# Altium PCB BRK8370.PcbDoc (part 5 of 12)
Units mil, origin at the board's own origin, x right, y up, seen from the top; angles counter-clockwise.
Board outline 8267.72 x 5708.66 mil, 6 copper layers (L1-TOP, L2-GND, L3-PWR, L4-PWR, L5-GND, L6-BOT), stack 68.606 mil thick; 319 components, 516 nets, 2008 pads, 1743 vias.
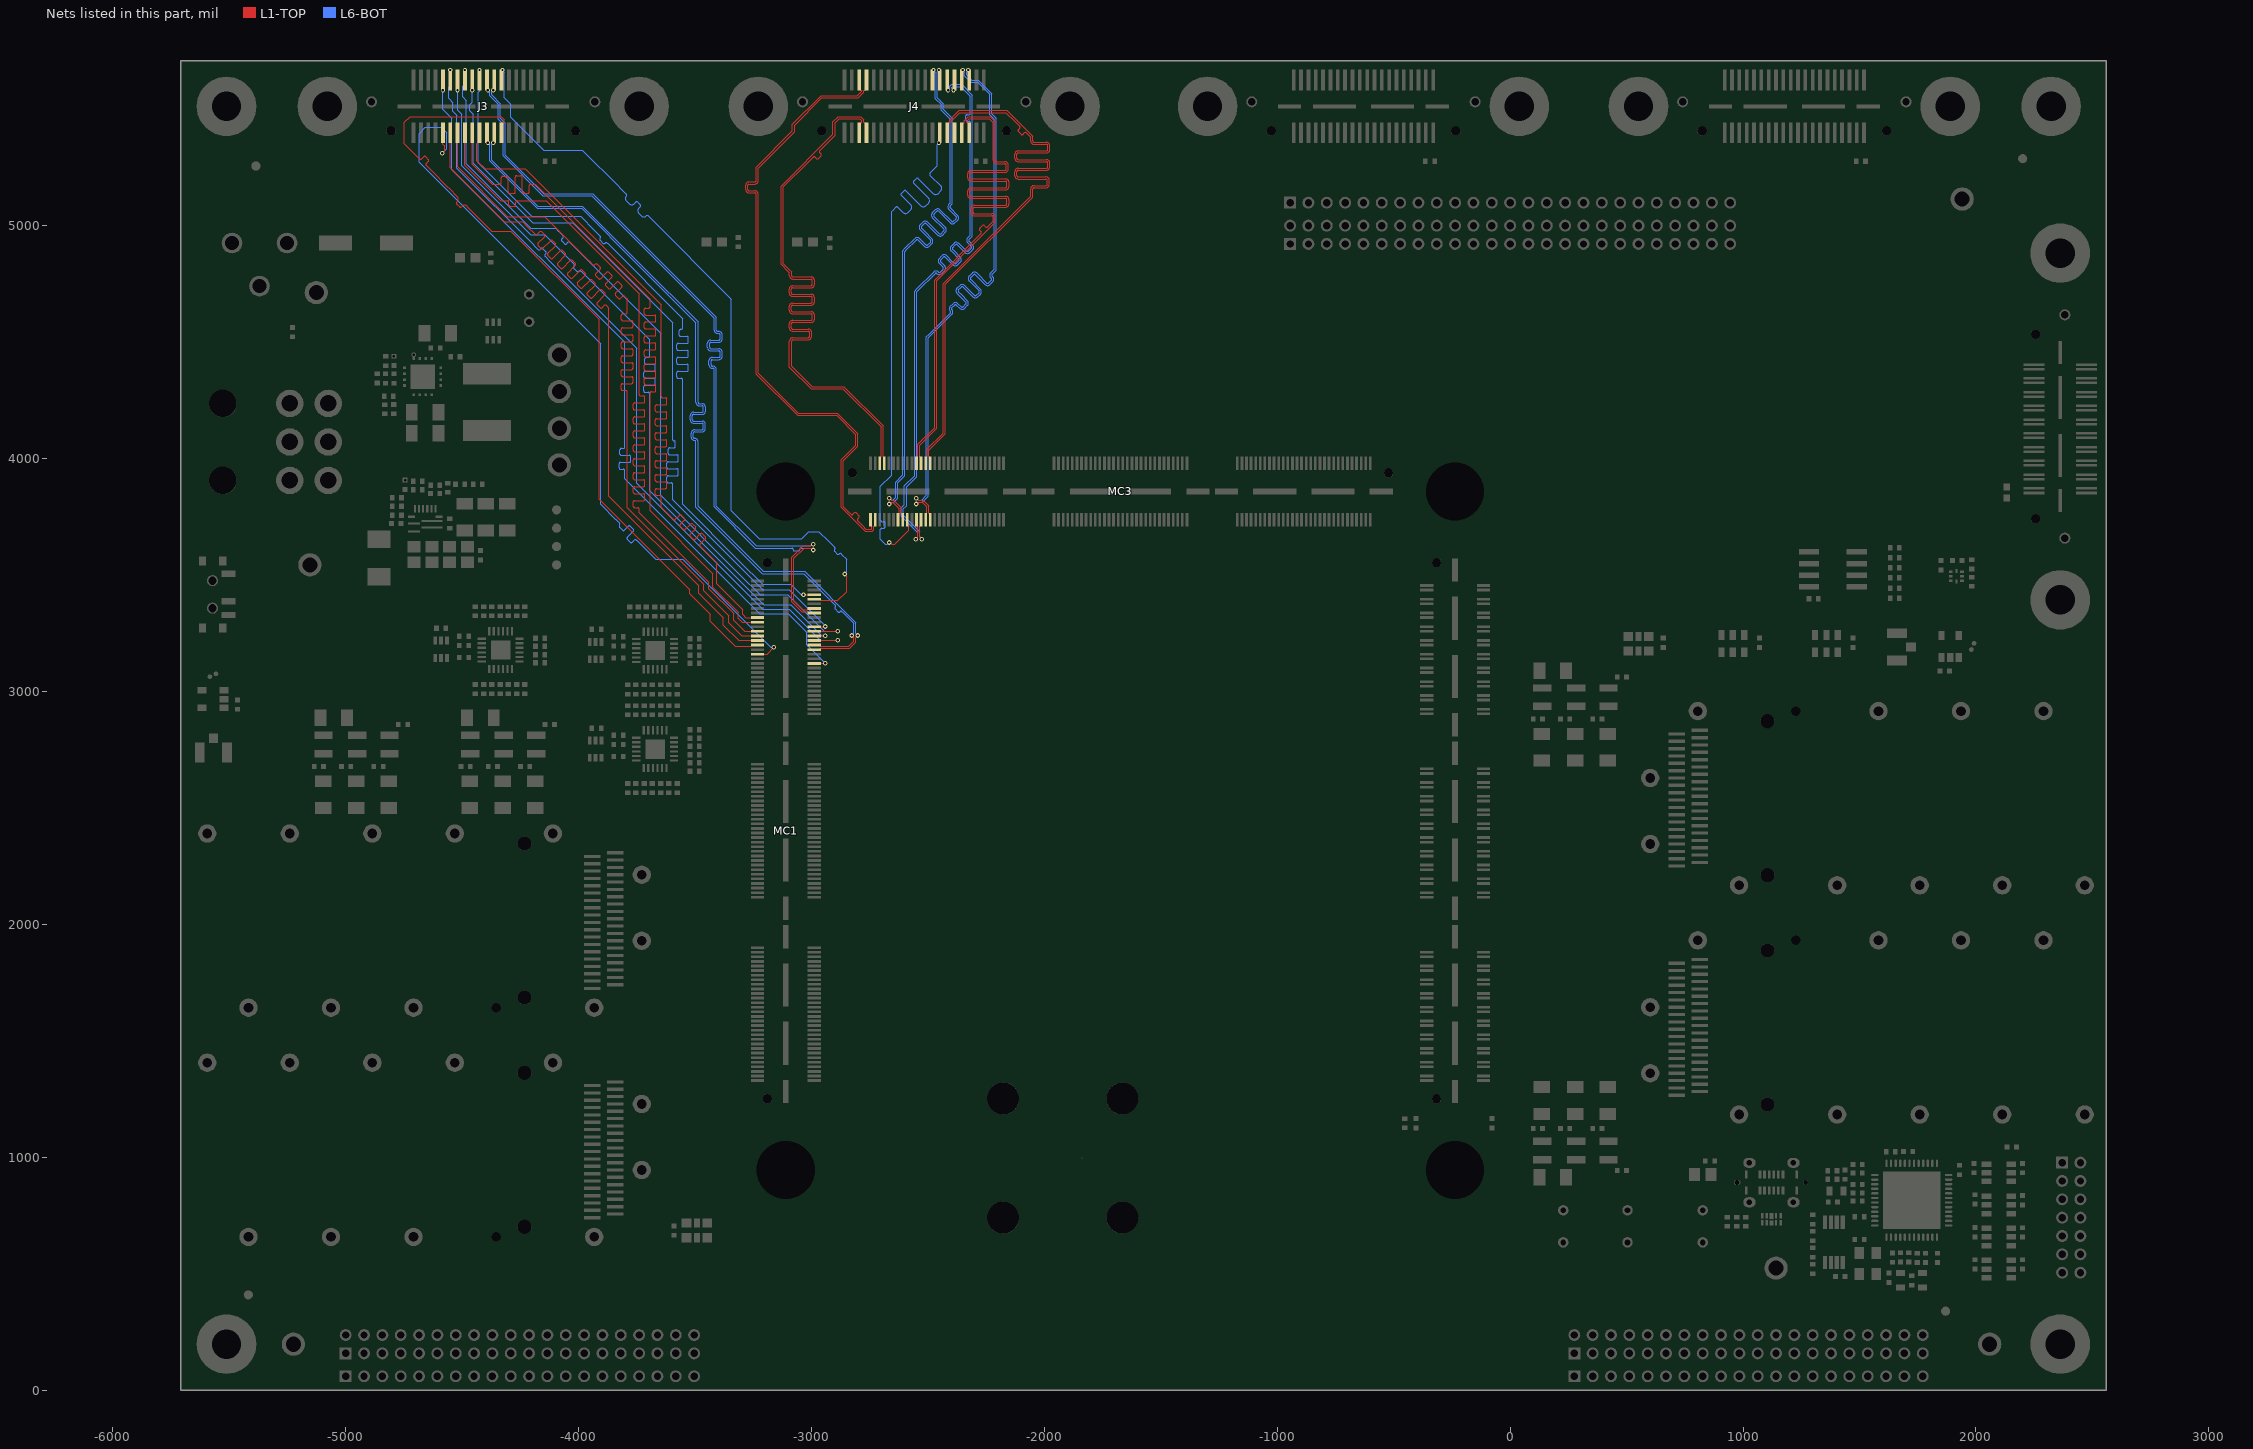
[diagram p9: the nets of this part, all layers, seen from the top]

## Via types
v1: diameter 20, hole 10, L1-TOP to L6-BOT, tented both sides, 957 vias
v2: diameter 18, hole 10, L1-TOP to L6-BOT, tented both sides, 786 vias

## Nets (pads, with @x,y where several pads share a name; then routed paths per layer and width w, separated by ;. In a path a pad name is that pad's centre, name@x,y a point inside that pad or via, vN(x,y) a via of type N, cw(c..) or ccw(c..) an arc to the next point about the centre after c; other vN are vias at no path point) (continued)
PORTA_S10_D4_N: J3.15 MC1.172 | length 3385.4
  L1-TOP w3.3: MC1.172@-2988.58,3395.67 -2965.94,3395.67 -2960.6,3390.33 -2887.61,3390.33 -2849.27,3428.67 -2849.27,3493.65 -2857.27,3501.65 v1(-2857.27,3503.94)
  L6-BOT w3.3: v2(-4326.43,5667.97) -4326.43,5665.72 -4319.4,5658.69 -4319.4,5549.17 -4290.29,5520.07 -4290.29,5464.95 -4149.86,5324.52 -3984.35,5324.52 -3827.76,5167.93 -3824.72,5164.9 -3794.61,5134.78 cw(c-3798.61,5130.78) -3794.61,5126.78 ccw(c-3784.24,5116.41) -3794.59,5106.02 -3782.63,5094.07 ccw(c-3772.24,5104.41) -3761.87,5094.04 -3755.05,5100.87 cw(c-3751.02,5096.89) -3747.02,5100.89 -3735.01,5088.88 cw(c-3739.01,5084.88) -3735.01,5080.88 -3741.86,5074.03 ccw(c-3731.49,5063.66) -3741.84,5053.27 -3729.88,5041.32 ccw(c-3719.49,5051.66) -3709.12,5041.29 cw(c-3705.12,5037.29) -3701.1,5041.27 ; -3701.09,5041.26 -3699.8,5039.97 -3696.77,5036.94 -3343.49,4683.66 -3343.49,3775.64 -3223.79,3655.95 -3042.49,3655.95 -3012.28,3686.16 -2968.04,3686.16 -2928.34,3646.46 -2900.43,3618.56 cw(c-2904.44,3614.56) -2900.43,3610.56 -2901.14,3609.85 ccw(c-2897.14,3605.85) -2901.14,3601.85 -2889.13,3589.84 ccw(c-2885.13,3593.84) -2881.13,3589.84 -2880.42,3590.55 cw(c-2876.42,3586.54) -2872.42,3590.55 -2871.25,3589.38 -2849.27,3567.4 -2849.27,3514.22 -2857.27,3506.22 v1(-2857.27,3503.94)
PORTA_S11_D5_N: J3.16 MC1.151 | length 3562.6
  L1-TOP w3.3: -4520.25,5123.94 -4558.08,5161.77 -4561.11,5164.8 -4633.2,5236.88 -4654.37,5258.06 cw(c-4650.37,5262.06) -4654.37,5266.06 -4644.7,5275.74 ccw(c-4648.7,5279.74) -4644.7,5283.74 -4656.71,5295.75 ccw(c-4660.71,5291.75) -4664.71,5295.75 -4674.39,5286.08 cw(c-4678.39,5290.08) -4682.39,5286.08 -4695.11,5298.79 -4748.03,5351.72 -4748.03,5443.48 -4723.4,5468.11 -4332.66,5468.11 -4319.4,5454.85 -4319.4,5444.04 -4321.33,5442.11 -4324.3,5442.11 -4330.65,5435.76 J3.16@-4330.65,5399.01 ; -4520.24,5123.92 -4518.94,5122.62 -4518.94,5122.43 cw(c-4530.62,5113.57) -4520.25,5103.21 -4523.32,5100.14 ccw(c-4519.32,5096.14) -4523.32,5092.15 -4511.31,5080.13 ccw(c-4507.31,5084.14) -4503.31,5080.13 -4500.24,5083.2 cw(c-4489.88,5072.83) -4481.02,5084.52 -4480.83,5084.52 -4479.53,5083.21 -4478.19,5081.88 -4475.16,5078.85 -4372.69,4976.38 -4291.34,4976.38 -3912.26,4597.3 -3912.26,3825.89 -3522.5,3436.13 -3522.5,3419.24 -3434.2,3330.94 -3434.2,3300.34 -3327.33,3193.48 -3259.87,3193.48 -3254.53,3198.82 MC1.151@-3231.89,3198.82
PORTA_S12_D6_P: J3.17 MC1.166 | length 3385.4
  L1-TOP w3.3: v1(-2992.13,3632.3) -2994.41,3632.3 -3002.41,3624.3 -3035.69,3624.3 -3084.93,3575.06 -3084.93,3385.57 -3041.32,3341.96 -3016.56,3341.96 -3011.22,3336.61 MC1.166@-2988.58,3336.61
  L6-BOT w3.3: v2(-4366.46,5581.25) -4366.46,5579.01 -4373.5,5571.97 -4373.5,5560.88 -4336.41,5523.8 -4336.41,5460.97 -4314.33,5438.88 -4314.33,5302.65 -4149.47,5137.8 -3940.03,5137.8 -3743.18,4940.94 -3408.32,4606.09 -3408.32,4557.53 -3408.32,4551.38 ccw(c-3402.66,4551.38) -3402.66,4545.72 -3397.98,4545.72 cw(c-3397.98,4531.06) -3383.32,4531.06 -3383.32,4514.08 cw(c-3397.98,4514.08) -3397.98,4499.42 -3432.17,4499.42 ccw(c-3432.17,4493.76) -3437.83,4493.76 -3437.83,4476.78 ccw(c-3432.17,4476.78) -3432.17,4471.12 -3397.98,4471.12 cw(c-3397.98,4456.46) -3383.32,4456.46 -3383.32,4439.48 cw(c-3397.98,4439.48) -3397.98,4424.82 -3425.64,4424.82 ccw(c-3425.64,4419.16) -3431.3,4419.16 -3431.3,4402.18 ccw(c-3425.64,4402.18) -3425.64,4396.52 -3422.98,4396.52 cw(c-3422.98,4381.86) -3408.32,4381.86 -3408.32,4305.4 -3408.32,3795.72 -3236.9,3624.3 -3002.41,3624.3 -2994.41,3632.3 v1(-2992.13,3632.3)
PORTA_S13_D7_P: J3.18 MC1.150 | length 3385.4
  L1-TOP w3.3: MC1.150@-2988.58,3179.13 -2965.94,3179.13 -2960.6,3184.48 -2836.64,3184.48 -2809.77,3211.34 -2809.77,3229.87 -2801.77,3237.87 v1(-2801.77,3240.16)
  L6-BOT w3.3: v2(-4366.46,5355.65) -4366.46,5353.41 -4373.5,5346.37 -4373.5,5281.36 -4174.82,5082.68 -3983.34,5082.68 -3735.3,4834.65 -3487.06,4586.41 -3487.06,4247.29 -3487.06,4241.14 ccw(c-3481.4,4241.14) -3481.4,4235.48 -3469.71,4235.48 cw(c-3469.71,4220.82) -3455.05,4220.82 -3455.05,4203.84 cw(c-3469.71,4203.84) -3469.71,4189.18 -3506.4,4189.18 ccw(c-3506.4,4183.52) -3512.06,4183.52 -3512.06,4166.54 ccw(c-3506.4,4166.54) -3506.4,4160.88 -3469.86,4160.88 cw(c-3469.86,4146.22) -3455.2,4146.22 -3455.2,4129.24 cw(c-3469.86,4129.24) -3469.86,4114.58 -3501.72,4114.58 ccw(c-3501.72,4108.92) -3507.38,4108.92 -3507.38,4091.94 ccw(c-3501.72,4091.94) -3501.72,4086.28 cw(c-3501.72,4071.62) -3487.06,4071.62 -3487.06,3997.2 -3487.06,3793.99 -3208.02,3514.95 -3029.19,3514.95 -2809.77,3295.53 -2809.77,3250.44 -2801.77,3242.44 v1(-2801.77,3240.16)
PORTA_S14_D6_N: J3.19 MC1.168 | length 3385.4
  L1-TOP w3.3: v1(-2992.13,3607.3) -2994.41,3607.3 -3002.41,3615.3 -3031.96,3615.3 -3075.93,3571.33 -3075.93,3389.3 -3037.59,3350.96 -3016.56,3350.96 -3011.22,3356.3 MC1.168@-2988.58,3356.3
  L6-BOT w3.3: v2(-4389.53,5581.25) -4389.53,5579.01 -4382.5,5571.97 -4382.5,5557.16 -4345.41,5520.07 -4345.41,5457.24 -4323.33,5435.15 -4323.33,5298.92 -4153.2,5128.8 -3943.76,5128.8 -3755.91,4940.95 -3417.32,4602.36 -3417.32,4557.53 -3417.32,4551.38 ccw(c-3402.66,4551.38) -3402.66,4536.72 -3397.98,4536.72 cw(c-3397.98,4531.06) -3392.32,4531.06 -3392.32,4514.08 cw(c-3397.98,4514.08) -3397.98,4508.42 -3432.17,4508.42 ccw(c-3432.17,4493.76) -3446.83,4493.76 -3446.83,4476.78 ccw(c-3432.17,4476.78) -3432.17,4462.12 -3397.98,4462.12 cw(c-3397.98,4456.46) -3392.32,4456.46 -3392.32,4439.48 cw(c-3397.98,4439.48) -3397.98,4433.82 -3425.64,4433.82 ccw(c-3425.64,4419.16) -3440.3,4419.16 -3440.3,4402.18 ccw(c-3425.64,4402.18) -3425.64,4387.52 -3422.98,4387.52 cw(c-3422.98,4381.86) -3417.32,4381.86 -3417.32,4305.4 -3417.32,3791.99 -3240.63,3615.3 -3102.36,3615.3 -3084.58,3615.3 cw(c-3084.58,3609.64) -3078.92,3609.64 -3078.92,3608.63 ccw(c-3073.26,3608.63) -3073.26,3602.97 -3056.28,3602.97 ccw(c-3056.28,3608.63) -3050.62,3608.63 -3050.62,3609.64 cw(c-3044.96,3609.64) -3044.96,3615.3 -3043.31,3615.3 -3002.41,3615.3 -2994.41,3607.3 v1(-2992.13,3607.3)
PORTA_S15_D7_N: J3.20 MC1.152 | length 3385.4
  L1-TOP w3.3: MC1.152@-2988.58,3198.82 -2965.94,3198.82 -2960.6,3193.48 -2840.37,3193.48 -2818.77,3215.07 -2818.77,3229.87 -2826.77,3237.87 v1(-2826.77,3240.16)
  L6-BOT w3.3: v2(-4389.53,5355.65) -4389.53,5353.41 -4382.5,5346.37 -4382.5,5277.63 -4178.55,5073.68 -3987.06,5073.68 -3748.03,4834.65 -3496.06,4582.68 -3496.06,4247.29 -3496.06,4241.14 ccw(c-3481.4,4241.14) -3481.4,4226.48 -3469.71,4226.48 cw(c-3469.71,4220.82) -3464.05,4220.82 -3464.05,4203.84 cw(c-3469.71,4203.84) -3469.71,4198.18 -3506.4,4198.18 ccw(c-3506.4,4183.52) -3521.06,4183.52 -3521.06,4166.54 ccw(c-3506.4,4166.54) -3506.4,4151.88 -3469.86,4151.88 cw(c-3469.86,4146.22) -3464.2,4146.22 -3464.2,4129.24 cw(c-3469.86,4129.24) -3469.86,4123.58 -3501.72,4123.58 ccw(c-3501.72,4108.92) -3516.38,4108.92 -3516.38,4091.94 ccw(c-3501.72,4091.94) -3501.72,4077.28 cw(c-3501.72,4071.62) -3496.06,4071.62 -3496.06,3997.2 -3496.06,3790.26 -3211.75,3505.95 -3032.92,3505.95 -2921.39,3394.42 -2897.51,3370.54 cw(c-2901.51,3366.54) -2897.51,3362.54 -2898.22,3361.83 ccw(c-2894.22,3357.83) -2898.22,3353.82 -2886.21,3341.82 ccw(c-2882.21,3345.82) -2878.21,3341.82 -2877.5,3342.53 cw(c-2873.5,3338.52) -2869.49,3342.53 -2868.33,3341.36 -2818.77,3291.8 -2818.77,3250.44 -2826.77,3242.44 v1(-2826.77,3240.16)
PORTA_S16: J3.21 MC1.174 | length 3379
  L1-TOP w4.96: v1(-3033.97,3414.88) -3033.74,3415.12 -2988.82,3415.12 MC1.174@-2988.58,3415.35
  L6-BOT w4.96: v2(-4425.25,5667.97) -4425.25,5578.79 -4431.15,5572.88 -4431.15,5270.32 -4200.2,5039.37 -3991.75,5039.37 -3932.88,4980.5 -3931.13,4978.75 -3907.21,4954.83 cw(c-3911.45,4950.6) -3907.21,4946.36 -3908.02,4945.55 ccw(c-3903.78,4941.31) -3908.02,4937.08 -3895.31,4924.36 ccw(c-3891.07,4928.6) -3886.83,4924.36 -3886.03,4925.17 cw(c-3881.79,4920.93) -3877.55,4925.17 -3875.8,4923.42 -3553.33,4600.95 -3553.33,4586.61 -3553.33,4560.09 cw(c-3559.32,4560.09) -3559.32,4554.1 -3561.79,4554.1 ccw(c-3561.79,4548.11) -3567.78,4548.11 -3567.78,4530.13 ccw(c-3561.79,4530.13) -3561.79,4524.14 -3534.32,4524.14 cw(c-3534.32,4518.15) -3528.33,4518.15 -3528.33,4500.17 cw(c-3534.32,4500.17) -3534.32,4494.18 -3572.33,4494.18 ccw(c-3572.33,4488.18) -3578.33,4488.18 -3578.33,4470.21 ccw(c-3572.33,4470.21) -3572.33,4464.21 -3534.32,4464.21 cw(c-3534.32,4458.22) -3528.33,4458.22 -3528.33,4440.24 cw(c-3534.32,4440.24) -3534.32,4434.25 -3572.33,4434.25 ccw(c-3572.33,4428.26) -3578.33,4428.26 -3578.33,4410.28 ccw(c-3572.33,4410.28) -3572.33,4404.29 -3534.32,4404.29 cw(c-3534.32,4398.29) -3528.33,4398.29 -3528.33,4380.32 cw(c-3534.32,4380.32) -3534.32,4374.32 -3572.33,4374.32 ccw(c-3572.33,4368.33) -3578.33,4368.33 -3578.33,4350.35 ccw(c-3572.33,4350.35) -3572.33,4344.36 -3559.32,4344.36 cw(c-3559.32,4338.37) -3553.33,4338.37 -3553.33,4335.89 -3553.33,3803.61 -3307.09,3557.37 -3209.95,3460.23 -3088,3460.23 -3045.53,3417.76 -3040,3417.76 v1@-3037.13,3414.88
PORTA_S17: J3.22 MC1.163 | length 3560.8
  L1-TOP w4.96: J3.22@-4425.15,5399.01 -4425.15,5362.26 -4437.01,5350.4 -4437.01,5279.53 -4401.57,5244.09 -4228.88,5244.09 -3645.67,4660.88 -3645.67,4279.53 -3645.67,4266.59 ccw(c-3639.68,4266.59) -3639.68,4260.6 -3626.66,4260.6 cw(c-3626.66,4254.61) -3620.67,4254.61 -3620.67,4236.63 cw(c-3626.66,4236.63) -3626.66,4230.64 -3664.68,4230.64 ccw(c-3664.68,4224.64) -3670.67,4224.64 -3670.67,4206.67 ccw(c-3664.68,4206.67) -3664.68,4200.67 -3626.66,4200.67 cw(c-3626.66,4194.68) -3620.67,4194.68 -3620.67,4176.7 cw(c-3626.66,4176.7) -3626.66,4170.71 -3664.68,4170.71 ccw(c-3664.68,4164.72) -3670.67,4164.72 -3670.67,4146.74 ccw(c-3664.68,4146.74) -3664.68,4140.75 -3626.66,4140.75 cw(c-3626.66,4134.76) -3620.67,4134.76 -3620.67,4116.78 cw(c-3626.66,4116.78) -3626.66,4110.78 -3664.68,4110.78 ccw(c-3664.68,4104.79) -3670.67,4104.79 -3670.67,4086.81 ccw(c-3664.68,4086.81) -3664.68,4080.82 -3626.66,4080.82 cw(c-3626.66,4074.83) -3620.67,4074.83 -3620.67,4056.85 cw(c-3626.66,4056.85) -3626.66,4050.86 -3664.68,4050.86 ccw(c-3664.68,4044.87) -3670.67,4044.87 -3670.67,4026.89 ccw(c-3664.68,4026.89) -3664.68,4020.9 -3626.66,4020.9 cw(c-3626.66,4014.9) -3620.67,4014.9 -3620.67,3996.93 cw(c-3626.66,3996.93) -3626.66,3990.93 -3664.68,3990.93 ccw(c-3664.68,3984.94) -3670.67,3984.94 -3670.67,3966.96 ccw(c-3664.68,3966.96) -3664.68,3960.97 -3626.66,3960.97 cw(c-3626.66,3954.98) -3620.67,3954.98 -3620.67,3937 cw(c-3626.66,3937) -3626.66,3931.01 -3664.68,3931.01 ccw(c-3664.68,3925.01) -3670.67,3925.01 -3670.67,3907.04 ccw(c-3664.68,3907.04) -3664.68,3901.04 -3626.66,3901.04 cw(c-3626.66,3895.05) -3620.67,3895.05 -3620.67,3877.07 cw(c-3626.66,3877.07) -3626.66,3871.08 -3664.68,3871.08 ccw(c-3664.68,3865.09) -3670.67,3865.09 -3670.67,3847.11 ccw(c-3664.68,3847.11) -3664.68,3841.12 -3651.66,3841.12 cw(c-3651.66,3835.13) -3645.67,3835.13 -3645.67,3832.64 -3645.67,3791.34 -3610.8,3756.47 -3609.05,3754.72 -3592.59,3738.26 ccw(c-3588.35,3742.49) -3584.11,3738.26 -3566.69,3755.68 cw(c-3562.45,3751.44) -3558.22,3755.68 -3545.5,3742.96 cw(c-3549.74,3738.73) -3545.5,3734.49 -3563.38,3716.62 ccw(c-3559.14,3712.38) -3563.38,3708.14 -3550.66,3695.43 ccw(c-3546.43,3699.67) -3542.19,3695.43 -3518.99,3718.63 cw(c-3514.75,3714.4) -3510.51,3718.63 -3497.8,3705.92 cw(c-3502.04,3701.68) -3497.8,3697.45 -3521,3674.24 ccw(c-3516.77,3670) -3521,3665.77 -3508.29,3653.05 ccw(c-3504.05,3657.29) -3499.82,3653.05 -3476.61,3676.26 cw(c-3472.37,3672.02) -3468.14,3676.26 -3455.42,3663.55 cw(c-3459.66,3659.31) -3455.42,3655.07 -3478.18,3632.32 ccw(c-3473.94,3628.08) -3478.18,3623.85 -3456.99,3602.66 -3455.23,3600.9 -3406.26,3551.92 -3406.26,3461.37 -3295.28,3350.39 -3295.28,3330.71 -3281.5,3316.93 MC1.163@-3231.89,3316.93
PORTA_S18: J3.23 MC1.160 | length 3381.6
  L1-TOP w4.96: MC1.160@-2988.85,3277.83 -2988.58,3278.1 -2940.69,3278.1 v1(-2940.42,3278.37)
  L6-BOT w4.96: v2(-4456.75,5581.25) -4456.75,5529.5 -4467.66,5518.58 -4467.66,5493.26 -4451.9,5477.5 -4451.9,5267.08 -4196.63,5011.81 -4025.44,5011.81 -3596.63,4583.01 -3596.63,4132.43 -3596.63,4081.47 ccw(c-3590.64,4081.47) -3590.64,4075.48 cw(c-3590.64,4069.49) -3584.65,4069.49 -3584.65,4051.51 cw(c-3590.64,4051.51) -3590.64,4045.52 -3609.35,4045.52 ccw(c-3609.35,4039.53) -3615.34,4039.53 -3615.34,4021.55 ccw(c-3609.35,4021.55) -3609.35,4015.56 -3577.63,4015.56 cw(c-3577.63,4009.56) -3571.63,4009.56 -3571.63,3991.59 cw(c-3577.63,3991.59) -3577.63,3985.59 -3615.64,3985.59 ccw(c-3615.64,3979.6) -3621.63,3979.6 -3621.63,3961.62 ccw(c-3615.64,3961.62) -3615.64,3955.63 -3577.63,3955.63 cw(c-3577.63,3949.64) -3571.63,3949.64 -3571.63,3931.66 cw(c-3577.63,3931.66) -3577.63,3925.67 -3615.64,3925.67 ccw(c-3615.64,3919.67) -3621.63,3919.67 -3621.63,3901.7 ccw(c-3615.64,3901.7) -3615.64,3895.7 -3602.63,3895.7 cw(c-3602.63,3889.71) -3596.63,3889.71 -3596.63,3887.23 -3596.63,3822.92 -3209.55,3435.84 -3094.66,3435.84 -2940.42,3281.6 v1(-2940.42,3278.37)
PORTA_S19: J3.24 MC1.161 | length 3558.2
  L1-TOP w4.96: J3.24@-4456.65,5399.01 -4456.65,5263.74 -4370.08,5177.17 -4360.99,5177.17 -4337.63,5177.17 ccw(c-4337.63,5183.16) -4331.64,5183.16 -4331.64,5206.21 cw(c-4325.65,5206.21) -4325.65,5212.2 -4307.67,5212.2 cw(c-4307.67,5206.21) -4301.68,5206.21 -4301.68,5145.26 ccw(c-4295.68,5145.26) -4295.68,5139.27 -4277.71,5139.27 ccw(c-4277.71,5145.26) -4271.71,5145.26 -4271.71,5208.14 cw(c-4265.72,5208.14) -4265.72,5214.13 -4247.74,5214.13 cw(c-4247.74,5208.14) -4241.75,5208.14 -4241.75,5145.26 ccw(c-4235.76,5145.26) -4235.76,5139.27 -4217.78,5139.27 ccw(c-4217.78,5145.26) -4211.79,5145.26 -4211.79,5171.17 cw(c-4205.8,5171.17) -4205.8,5177.17 -4203.31,5177.17 -4185.94,5177.17 -3692.91,4684.14 -3692.91,4652.02 cw(c-3698.91,4652.02) -3698.91,4646.03 -3711.92,4646.03 ccw(c-3711.92,4640.03) -3717.91,4640.03 -3717.91,4622.05 ccw(c-3711.92,4622.05) -3711.92,4616.06 -3673.91,4616.06 cw(c-3673.91,4610.07) -3667.91,4610.07 -3667.91,4592.09 cw(c-3673.91,4592.09) -3673.91,4586.1 -3711.92,4586.1 ccw(c-3711.92,4580.11) -3717.91,4580.11 -3717.91,4562.13 ccw(c-3711.92,4562.13) -3711.92,4556.14 -3673.91,4556.14 cw(c-3673.91,4550.14) -3667.91,4550.14 -3667.91,4532.17 cw(c-3673.91,4532.17) -3673.91,4526.17 -3711.92,4526.17 ccw(c-3711.92,4520.18) -3717.91,4520.18 -3717.91,4502.2 ccw(c-3711.92,4502.2) -3711.92,4496.21 -3673.91,4496.21 cw(c-3673.91,4490.22) -3667.91,4490.22 -3667.91,4472.24 cw(c-3673.91,4472.24) -3673.91,4466.25 -3711.92,4466.25 ccw(c-3711.92,4460.25) -3717.91,4460.25 -3717.91,4442.28 ccw(c-3711.92,4442.28) -3711.92,4436.28 -3673.91,4436.28 cw(c-3673.91,4430.29) -3667.91,4430.29 -3667.91,4412.31 cw(c-3673.91,4412.31) -3673.91,4406.32 -3711.92,4406.32 ccw(c-3711.92,4400.33) -3717.91,4400.33 -3717.91,4382.35 ccw(c-3711.92,4382.35) -3711.92,4376.36 -3673.91,4376.36 cw(c-3673.91,4370.37) -3667.91,4370.37 -3667.91,4352.39 cw(c-3673.91,4352.39) -3673.91,4346.4 -3711.92,4346.4 ccw(c-3711.92,4340.4) -3717.91,4340.4 -3717.91,4322.42 ccw(c-3711.92,4322.42) -3711.92,4316.43 -3673.91,4316.43 cw(c-3673.91,4310.44) -3667.91,4310.44 -3667.91,4292.46 cw(c-3673.91,4292.46) -3673.91,4286.47 -3686.92,4286.47 ccw(c-3686.92,4280.48) -3692.91,4280.48 -3692.91,4248.03 -3692.91,3775.59 -3423.22,3505.9 -3423.22,3447.71 -3314.96,3339.45 -3314.96,3314.96 -3297.24,3297.24 MC1.161@-3231.89,3297.24
PORTA_S20: J3.25 MC1.158 | length 3381.6
  L1-TOP w4.96: MC1.158@-2988.85,3258.14 MC1.158@-2988.58,3257.87 -2887.25,3257.87 v1(-2886.56,3258.57)
  L6-BOT w4.96: v2(-4488.25,5667.97) -4488.25,5608.83 -4498.26,5598.82 -4498.26,5552.88 -4481.97,5536.59 -4481.97,5308.07 -4481.97,5265.43 -4204.72,4988.19 -4097.75,4988.19 -4086.28,4976.72 -4084.52,4974.96 -4066.68,4957.13 cw(c-4070.92,4952.89) -4066.68,4948.65 -4072.9,4942.44 ccw(c-4068.66,4938.2) -4072.9,4933.96 -4060.19,4921.25 ccw(c-4055.95,4925.49) -4051.71,4921.25 -4045.5,4927.46 cw(c-4041.26,4923.23) -4037.02,4927.46 -4035.27,4925.71 -3647.81,4538.26 -3647.81,3842.47 -3307.09,3501.74 -3220.93,3415.58 -3102.36,3415.58 -2945.34,3258.57 v1(-2886.56,3258.57)
PORTA_S21: J3.26 MC1.157 | length 3558.2
  L1-TOP w4.96: J3.26@-4488.15,5399.01 -4488.15,5259.8 -4334.65,5106.3 -4314.96,5106.3 -4304.87,5106.3 cw(c-4304.87,5100.31) -4298.88,5100.31 -4298.88,5088.06 ccw(c-4292.89,5088.06) -4292.89,5082.07 -4274.91,5082.07 ccw(c-4274.91,5088.06) -4268.92,5088.06 -4268.92,5100.31 cw(c-4262.92,5100.31) -4262.92,5106.3 -4260.44,5106.3 -4139.06,5106.3 -3740.16,4707.39 -3740.16,4303.15 -3740.16,4274.62 ccw(c-3734.16,4274.62) -3734.16,4268.62 -3721.15,4268.62 cw(c-3721.15,4262.63) -3715.16,4262.63 -3715.16,4244.65 cw(c-3721.15,4244.65) -3721.15,4238.66 -3759.16,4238.66 ccw(c-3759.16,4232.67) -3765.16,4232.67 -3765.16,4214.69 ccw(c-3759.16,4214.69) -3759.16,4208.7 -3721.15,4208.7 cw(c-3721.15,4202.71) -3715.16,4202.71 -3715.16,4184.73 cw(c-3721.15,4184.73) -3721.15,4178.74 -3759.16,4178.74 ccw(c-3759.16,4172.74) -3765.16,4172.74 -3765.16,4154.76 ccw(c-3759.16,4154.76) -3759.16,4148.77 -3721.15,4148.77 cw(c-3721.15,4142.78) -3715.16,4142.78 -3715.16,4124.8 cw(c-3721.15,4124.8) -3721.15,4118.81 -3759.16,4118.81 ccw(c-3759.16,4112.82) -3765.16,4112.82 -3765.16,4094.84 ccw(c-3759.16,4094.84) -3759.16,4088.85 -3721.15,4088.85 cw(c-3721.15,4082.85) -3715.16,4082.85 -3715.16,4064.88 cw(c-3721.15,4064.88) -3721.15,4058.88 -3759.16,4058.88 ccw(c-3759.16,4052.89) -3765.16,4052.89 -3765.16,4034.91 ccw(c-3759.16,4034.91) -3759.16,4028.92 -3721.15,4028.92 cw(c-3721.15,4022.93) -3715.16,4022.93 -3715.16,4004.95 cw(c-3721.15,4004.95) -3721.15,3998.96 -3759.16,3998.96 ccw(c-3759.16,3992.96) -3765.16,3992.96 -3765.16,3974.99 ccw(c-3759.16,3974.99) -3759.16,3968.99 -3721.15,3968.99 cw(c-3721.15,3963) -3715.16,3963 -3715.16,3945.02 cw(c-3721.15,3945.02) -3721.15,3939.03 -3759.16,3939.03 ccw(c-3759.16,3933.04) -3765.16,3933.04 -3765.16,3915.06 ccw(c-3759.16,3915.06) -3759.16,3909.07 -3721.15,3909.07 cw(c-3721.15,3903.08) -3715.16,3903.08 -3715.16,3885.1 cw(c-3721.15,3885.1) -3721.15,3879.11 -3759.16,3879.11 ccw(c-3759.16,3873.11) -3765.16,3873.11 -3765.16,3855.13 ccw(c-3759.16,3855.13) -3759.16,3849.14 -3721.15,3849.14 cw(c-3721.15,3843.15) -3715.16,3843.15 -3715.16,3825.17 cw(c-3721.15,3825.17) -3721.15,3819.18 -3759.16,3819.18 ccw(c-3759.16,3813.19) -3765.16,3813.19 -3765.16,3795.21 ccw(c-3759.16,3795.21) -3759.16,3789.22 -3746.15,3789.22 cw(c-3746.15,3783.22) -3740.16,3783.22 -3740.16,3780.74 -3740.16,3767.75 -3440.18,3467.77 -3440.18,3440.68 -3333.88,3334.38 -3333.88,3306.22 -3285.53,3257.87 MC1.157@-3231.89,3257.87
PORTA_S22: J3.27 MC1.156 | length 3381.6
  L1-TOP w4.96: MC1.156@-2988.85,3238.46 -2988.58,3238.73 -2940.69,3238.73 v1(-2940.42,3239)
  L6-BOT w4.96: v2(-4519.75,5581.25) -4519.75,5496.13 -4501.59,5477.97 -4501.59,5308.07 -4501.59,5257.5 -4204.72,4960.63 -4145.67,4960.63 -4055.12,4870.08 -4053.36,4868.32 -4019.61,4834.57 cw(c-4023.84,4830.33) -4019.61,4826.09 -4020.41,4825.28 ccw(c-4016.18,4821.05) -4020.41,4816.81 -4007.7,4804.1 ccw(c-4003.46,4808.33) -3999.23,4804.1 -3998.42,4804.9 cw(c-3994.18,4800.67) -3989.94,4804.9 -3988.19,4803.15 -3695.06,4510.02 -3695.06,4492.13 -3695.06,4439.87 cw(c-3701.05,4439.87) -3701.05,4433.88 -3708.98,4433.88 ccw(c-3708.98,4427.89) -3714.97,4427.89 -3714.97,4409.91 ccw(c-3708.98,4409.91) -3708.98,4403.92 -3676.05,4403.92 cw(c-3676.05,4397.92) -3670.06,4397.92 -3670.06,4379.95 cw(c-3676.05,4379.95) -3676.05,4373.95 -3714.07,4373.95 ccw(c-3714.07,4367.96) -3720.06,4367.96 -3720.06,4349.98 ccw(c-3714.07,4349.98) -3714.07,4343.99 -3676.05,4343.99 cw(c-3676.05,4338) -3670.06,4338 -3670.06,4320.02 cw(c-3676.05,4320.02) -3676.05,4314.03 -3714.07,4314.03 ccw(c-3714.07,4308.04) -3720.06,4308.04 -3720.06,4290.06 ccw(c-3714.07,4290.06) -3714.07,4284.07 -3701.05,4284.07 cw(c-3701.05,4278.07) -3695.06,4278.07 -3695.06,4275.59 -3695.06,3862.16 -3307.09,3474.18 -3204.74,3371.84 -3088.37,3371.84 -2955.53,3239 v1(-2940.42,3239)
PORTA_S23: J3.28 MC1.155 | length 3558.2
  L1-TOP w4.96: J3.28@-4519.65,5399.01 -4519.65,5251.93 -4305.66,5037.95 -4144.25,5037.95 -3956.31,4850.01 -3954.55,4848.25 -3938.53,4832.23 ccw(c-3934.3,4836.47) -3930.06,4832.23 -3928.84,4833.45 cw(c-3924.6,4829.22) -3920.36,4833.45 -3907.65,4820.74 cw(c-3911.89,4816.5) -3907.65,4812.27 -3926.55,4793.37 ccw(c-3922.31,4789.13) -3926.55,4784.89 -3913.84,4772.18 ccw(c-3909.6,4776.42) -3905.36,4772.18 -3878.48,4799.06 cw(c-3874.24,4794.83) -3870.01,4799.06 -3857.29,4786.35 cw(c-3861.53,4782.11) -3857.29,4777.88 -3884.17,4751 ccw(c-3879.94,4746.76) -3884.17,4742.52 -3871.46,4729.81 ccw(c-3867.23,4734.05) -3862.99,4729.81 -3836.11,4756.69 cw(c-3831.87,4752.45) -3827.63,4756.69 -3814.92,4743.98 cw(c-3819.16,4739.74) -3814.92,4735.5 -3841.8,4708.62 ccw(c-3837.56,4704.38) -3841.8,4700.15 -3829.09,4687.43 ccw(c-3824.85,4691.67) -3820.61,4687.43 -3811.41,4696.64 cw(c-3807.17,4692.4) -3802.94,4696.64 -3801.18,4694.88 -3791.34,4685.04 -3791.34,4659.19 -3791.34,4627.52 cw(c-3797.33,4627.52) -3797.33,4621.53 -3810.35,4621.53 ccw(c-3810.35,4615.54) -3816.34,4615.54 -3816.34,4597.56 ccw(c-3810.35,4597.56) -3810.35,4591.57 -3772.33,4591.57 cw(c-3772.33,4585.58) -3766.34,4585.58 -3766.34,4567.6 cw(c-3772.33,4567.6) -3772.33,4561.61 -3810.35,4561.61 ccw(c-3810.35,4555.61) -3816.34,4555.61 -3816.34,4537.64 ccw(c-3810.35,4537.64) -3810.35,4531.64 -3772.33,4531.64 cw(c-3772.33,4525.65) -3766.34,4525.65 -3766.34,4507.67 cw(c-3772.33,4507.67) -3772.33,4501.68 -3810.35,4501.68 ccw(c-3810.35,4495.69) -3816.34,4495.69 -3816.34,4477.71 ccw(c-3810.35,4477.71) -3810.35,4471.72 -3772.33,4471.72 cw(c-3772.33,4465.72) -3766.34,4465.72 -3766.34,4447.75 cw(c-3772.33,4447.75) -3772.33,4441.75 -3810.35,4441.75 ccw(c-3810.35,4435.76) -3816.34,4435.76 -3816.34,4417.78 ccw(c-3810.35,4417.78) -3810.35,4411.79 -3772.33,4411.79 cw(c-3772.33,4405.8) -3766.34,4405.8 -3766.34,4387.82 cw(c-3772.33,4387.82) -3772.33,4381.83 -3810.35,4381.83 ccw(c-3810.35,4375.84) -3816.34,4375.84 -3816.34,4357.86 ccw(c-3810.35,4357.86) -3810.35,4351.87 -3772.33,4351.87 cw(c-3772.33,4345.87) -3766.34,4345.87 -3766.34,4327.89 cw(c-3772.33,4327.89) -3772.33,4321.9 -3810.35,4321.9 ccw(c-3810.35,4315.91) -3816.34,4315.91 -3816.34,4297.93 ccw(c-3810.35,4297.93) -3810.35,4291.94 -3797.33,4291.94 cw(c-3797.33,4285.95) -3791.34,4285.95 -3791.34,4283.46 -3791.34,3788.5 -3462.38,3459.54 -3462.38,3431.48 -3356.08,3325.18 -3356.08,3294.54 -3299.73,3238.19 MC1.155@-3231.89,3238.19
PORTA_S24: J3.29 MC1.154 | length 3381.6
  L1-TOP w4.96: MC1.154@-2988.85,3218.77 MC1.154@-2988.58,3218.5 -2887.25,3218.5 v1(-2886.56,3219.2)
  L6-BOT w4.96: v2(-4551.25,5667.97) -4551.25,5600.12 -4557.83,5593.54 -4557.83,5545.76 -4539.59,5527.52 -4539.59,5490.17 -4523.62,5474.2 -4523.62,5308.07 -4523.62,5246.99 -4193.43,4916.8 -4191.68,4915.05 -4173.87,4897.23 ccw(c-4169.63,4901.47) -4165.39,4897.23 -4161.61,4901.02 cw(c-4157.37,4896.78) -4153.13,4901.02 -4140.42,4888.3 cw(c-4144.66,4884.07) -4140.42,4879.83 -4144.21,4876.05 ccw(c-4139.97,4871.81) -4144.21,4867.57 -4123.02,4846.39 -4121.26,4844.63 -3750.18,4473.54 -3750.18,3893.65 -3307.09,3450.56 -3209.22,3352.7 -3094.92,3352.7 -2961.42,3219.2 v1(-2886.56,3219.2)
PORTA_S25: J3.30 MC1.153 | length 3558.2
  L1-TOP w4.96: J3.30@-4551.15,5399.01 -4551.15,5248 -4318.9,5015.75 -4240.16,5015.75 -4224.41,5000 -4222.65,4998.25 -4186.56,4962.15 ccw(c-4182.32,4966.38) -4178.08,4962.15 -4167.3,4972.93 cw(c-4163.06,4968.69) -4158.83,4972.93 -4146.11,4960.21 cw(c-4150.35,4955.98) -4146.11,4951.74 -4174.57,4923.28 ccw(c-4170.33,4919.04) -4174.57,4914.81 -4161.86,4902.09 ccw(c-4157.62,4906.33) -4153.38,4902.09 -4120,4935.48 cw(c-4115.77,4931.24) -4111.53,4935.48 -4098.82,4922.76 cw(c-4103.05,4918.53) -4098.82,4914.29 -4132.2,4880.91 ccw(c-4127.96,4876.67) -4132.2,4872.43 -4119.49,4859.72 ccw(c-4115.25,4863.96) -4111.01,4859.72 -4077.63,4893.1 cw(c-4073.39,4888.86) -4069.16,4893.1 -4056.44,4880.39 cw(c-4060.68,4876.15) -4056.44,4871.91 -4089.82,4838.53 ccw(c-4085.59,4834.3) -4089.82,4830.06 -4077.11,4817.35 ccw(c-4072.87,4821.58) -4068.64,4817.35 -4035.26,4850.73 cw(c-4031.02,4846.49) -4026.78,4850.73 -4014.07,4838.02 cw(c-4018.31,4833.78) -4014.07,4829.54 -4047.45,4796.16 ccw(c-4043.21,4791.92) -4047.45,4787.68 -4034.74,4774.97 ccw(c-4030.5,4779.21) -4026.26,4774.97 -3992.88,4808.35 cw(c-3988.64,4804.12) -3984.41,4808.35 -3971.69,4795.64 cw(c-3975.93,4791.4) -3971.69,4787.17 -4005.08,4753.79 ccw(c-4000.84,4749.55) -4005.08,4745.31 -3992.36,4732.6 ccw(c-3988.13,4736.84) -3983.89,4732.6 -3950.51,4765.98 cw(c-3946.27,4761.74) -3942.03,4765.98 -3929.32,4753.27 cw(c-3933.56,4749.03) -3929.32,4744.79 -3962.7,4711.41 ccw(c-3958.46,4707.17) -3962.7,4702.94 -3949.99,4690.22 ccw(c-3945.75,4694.46) -3941.51,4690.22 -3908.13,4723.61 cw(c-3903.9,4719.37) -3899.66,4723.61 -3886.95,4710.89 ; -3886.95,4710.89 cw(c-3891.18,4706.66) -3886.95,4702.42 -3920.33,4669.04 ccw(c-3916.09,4664.8) -3920.33,4660.56 -3907.62,4647.85 ccw(c-3903.38,4652.09) -3899.14,4647.85 -3889.94,4657.05 cw(c-3885.7,4652.82) -3881.46,4657.05 -3879.71,4655.3 -3870.08,4645.67 -3870.08,3838.48 -3484.58,3452.98 -3484.58,3422.29 -3378.28,3315.99 -3378.28,3283.79 -3312.99,3218.5 MC1.153@-3231.89,3218.5
PORTA_S26: J3.31 MC1.144 | length 3381.6
  L1-TOP w4.96: MC1.144@-2988.85,3120.35 -2988.58,3120.62 -2940.69,3120.62 v1(-2940.42,3120.89)
  L6-BOT w4.96: v2(-4582.75,5581.25) -4582.75,5499.55 -4543.81,5460.61 -4543.81,5240.66 -3801.36,4498.21 -3801.36,4107.94 -3801.36,4049.18 cw(c-3807.35,4049.18) -3807.35,4043.19 -3816.25,4043.19 ccw(c-3816.25,4037.2) -3822.24,4037.2 -3822.24,4019.22 ccw(c-3816.25,4019.22) -3816.25,4013.23 -3782.35,4013.23 cw(c-3782.35,4007.24) -3776.36,4007.24 -3776.36,3989.26 cw(c-3782.35,3989.26) -3782.35,3983.27 -3820.36,3983.27 ccw(c-3820.36,3977.27) -3826.36,3977.27 -3826.36,3959.3 ccw(c-3820.36,3959.3) -3820.36,3953.3 -3807.35,3953.3 cw(c-3807.35,3947.31) -3801.36,3947.31 -3801.36,3944.83 -3801.36,3913.71 -3221.66,3334.02 -3100.19,3334.02 -3019.68,3253.51 -3019.68,3200.15 v1(-2940.42,3120.89)
PORTA_S27: J3.32 MC1.147 | length 3423.8
  L1-TOP w4.96: v1(-4584.88,5310.99) -4574.8,5321.07 -4574.8,5342.52 -4582.65,5350.37 J3.32@-4582.65,5399.01 ; MC1.147@-3231.89,3159.45 -3190.94,3159.45 v1(-3161.42,3188.98)
  L6-BOT w4.96: v1(-4584.88,5310.99) -4566.93,5328.94 -4566.93,5397.64 -4590.55,5421.26 -4657.48,5421.26 -4685.04,5393.7 -4685.04,5271.65 -3905.51,4492.13 -3905.51,3803.15 -3842.23,3739.87 -3840.48,3738.11 -3824.1,3721.74 cw(c-3828.34,3717.5) -3824.1,3713.26 ccw(c-3819.86,3709.02) -3824.1,3704.79 -3811.39,3692.07 ccw(c-3807.15,3696.31) -3802.91,3692.07 -3786.32,3708.67 cw(c-3782.08,3704.43) -3777.84,3708.67 -3765.13,3695.96 cw(c-3769.37,3691.72) -3765.13,3687.48 -3790.93,3661.68 ccw(c-3786.69,3657.45) -3790.93,3653.21 -3778.21,3640.5 ccw(c-3773.98,3644.73) -3769.74,3640.5 -3760.54,3649.7 cw(c-3756.3,3645.46) -3752.06,3649.7 -3750.31,3647.94 -3669.29,3566.93 -3553.7,3566.93 -3175.75,3188.98 v1(-3161.42,3188.98)
PORTB_C2P_CLK_N: J4.36 MC3.7 | length 2726.1
  L1-TOP w3.3: J4.36@-2795.26,5399.01 -2795.26,5435.76 -2788.91,5442.11 -2785.94,5442.11 -2784.01,5444.04 -2784.01,5449.92 -2792.53,5458.45 -2881.73,5458.45 -2898.76,5441.41 -2898.76,5387.72 -2956.23,5330.25 -2964.74,5321.74 ccw(c-2960.74,5317.74) -2964.74,5313.74 -2958.77,5307.76 cw(c-2962.77,5303.76) -2958.77,5299.76 -2970.77,5287.75 cw(c-2974.78,5291.75) -2978.78,5287.75 -2984.75,5293.73 ccw(c-2988.76,5289.72) -2992.76,5293.73 -3013.94,5272.55 -3120.56,5165.93 -3120.56,4837.09 -3094.49,4811.02 -3085.49,4802.02 -3085.49,4791.34 -3085.49,4785.19 ccw(c-3079.83,4785.19) -3079.83,4779.53 -3001.6,4779.53 cw(c-3001.6,4764.87) -2986.94,4764.87 -2986.94,4747.89 cw(c-3001.6,4747.89) -3001.6,4733.23 -3081.01,4733.23 ccw(c-3081.01,4727.57) -3086.67,4727.57 -3086.67,4710.59 ccw(c-3081.01,4710.59) -3081.01,4704.93 -3001.6,4704.93 cw(c-3001.6,4690.27) -2986.94,4690.27 -2986.94,4673.29 cw(c-3001.6,4673.29) -3001.6,4658.63 -3081.01,4658.63 ccw(c-3081.01,4652.97) -3086.67,4652.97 -3086.67,4635.99 ccw(c-3081.01,4635.99) -3081.01,4630.33 -3001.6,4630.33 cw(c-3001.6,4615.67) -2986.94,4615.67 -2986.94,4598.69 cw(c-3001.6,4598.69) -3001.6,4584.03 -3081.01,4584.03 ccw(c-3081.01,4578.37) -3086.67,4578.37 -3086.67,4561.39 ccw(c-3081.01,4561.39) -3081.01,4555.73 -3014,4555.73 cw(c-3014,4541.07) -2999.34,4541.07 -2999.34,4524.09 cw(c-3014,4524.09) -3014,4509.43 -3079.83,4509.43 ccw(c-3079.83,4503.77) -3085.49,4503.77 -3085.49,4421.26 -3085.49,4396.51 -2997.19,4308.21 -2860.98,4308.21 -2692.35,4139.58 -2692.35,4007.9 -2687.01,4002.56 MC3.7@-2687.01,3979.92
PORTB_C2P_CLK_P: J4.34 MC3.5 | length 2726.1
  L1-TOP w3.3: J4.34@-2763.76,5399.01 -2763.76,5435.76 -2770.11,5442.11 -2773.07,5442.11 -2775.01,5444.04 -2775.01,5453.64 -2788.81,5467.45 -2885.46,5467.45 -2907.76,5445.14 -2907.76,5391.45 -3129.56,5169.66 -3129.56,4833.37 -3100.85,4804.66 -3094.49,4798.3 -3094.49,4791.34 -3094.49,4785.19 ccw(c-3079.83,4785.19) -3079.83,4770.53 -3001.6,4770.53 cw(c-3001.6,4764.87) -2995.94,4764.87 -2995.94,4747.89 cw(c-3001.6,4747.89) -3001.6,4742.23 -3081.01,4742.23 ccw(c-3081.01,4727.57) -3095.67,4727.57 -3095.67,4710.59 ccw(c-3081.01,4710.59) -3081.01,4695.93 -3001.6,4695.93 cw(c-3001.6,4690.27) -2995.94,4690.27 -2995.94,4673.29 cw(c-3001.6,4673.29) -3001.6,4667.63 -3081.01,4667.63 ccw(c-3081.01,4652.97) -3095.67,4652.97 -3095.67,4635.99 ccw(c-3081.01,4635.99) -3081.01,4621.33 -3001.6,4621.33 cw(c-3001.6,4615.67) -2995.94,4615.67 -2995.94,4598.69 cw(c-3001.6,4598.69) -3001.6,4593.03 -3081.01,4593.03 ccw(c-3081.01,4578.37) -3095.67,4578.37 -3095.67,4561.39 ccw(c-3081.01,4561.39) -3081.01,4546.73 -3014,4546.73 cw(c-3014,4541.07) -3008.34,4541.07 -3008.34,4524.09 cw(c-3014,4524.09) -3014,4518.43 -3079.83,4518.43 ccw(c-3079.83,4503.77) -3094.49,4503.77 -3094.49,4421.26 -3094.49,4392.78 -3000.92,4299.21 -2864.71,4299.21 -2701.35,4135.85 -2701.35,4007.9 -2706.69,4002.56 MC3.5@-2706.69,3979.92
PORTB_P2C_CLK_N: J4.35 MC3.4 | length 2726.2
  L1-TOP w3.3: J4.35@-2795.31,5624.61 -2795.31,5587.91 -2788.91,5581.51 -2785.94,5581.51 -2784.01,5579.58 -2784.01,5576.11 -2802.8,5557.32 -2958.92,5557.32 -3081.55,5434.68 -3081.55,5406.64 -3237.35,5250.84 -3237.35,5240.16 -3237.35,5193 cw(c-3243.01,5193) -3243.01,5187.34 -3268.32,5187.34 ccw(c-3268.32,5172.68) -3282.98,5172.68 -3282.98,5155.7 ccw(c-3268.32,5155.7) -3268.32,5141.04 -3243.01,5141.04 cw(c-3243.01,5135.38) -3237.35,5135.38 -3237.35,5129.23 -3237.35,4362.41 -3059.97,4185.04 -2892.11,4185.04 -2809.9,4102.83 -2809.9,4055.98 -2872.34,3993.54 -2872.34,3789.71 -2769.8,3687.17 -2738.93,3687.17 -2731.72,3694.38 -2731.72,3708.63 -2726.38,3713.98 MC3.4@-2726.38,3736.61
PORTB_P2C_CLK_P: J4.33 MC3.2 | length 2726.1
  L1-TOP w3.3: J4.33@-2763.81,5624.61 -2763.81,5587.81 -2770.11,5581.51 -2773.07,5581.51 -2775.01,5579.58 -2775.01,5572.38 -2799.07,5548.32 -2955.19,5548.32 -3072.55,5430.96 -3072.55,5402.91 -3228.35,5247.11 -3228.35,5240.16 -3228.35,5193 cw(c-3243.01,5193) -3243.01,5178.34 -3268.32,5178.34 ccw(c-3268.32,5172.68) -3273.98,5172.68 -3273.98,5155.7 ccw(c-3268.32,5155.7) -3268.32,5150.04 -3243.01,5150.04 cw(c-3243.01,5135.38) -3228.35,5135.38 -3228.35,5129.23 -3228.35,4366.14 -3056.24,4194.04 -2888.38,4194.04 -2800.9,4106.56 -2800.9,4052.25 -2863.34,3989.81 -2863.34,3793.44 -2842.04,3772.14 -2830.07,3760.16 ccw(c-2826.06,3764.17) -2822.06,3760.16 -2816.09,3766.14 cw(c-2812.08,3762.14) -2808.08,3766.14 -2796.08,3754.13 cw(c-2800.08,3750.13) -2796.07,3746.13 -2802.05,3740.15 ccw(c-2798.05,3736.15) -2802.05,3732.15 -2780.87,3710.97 -2766.07,3696.17 -2742.65,3696.17 -2740.72,3698.1 -2740.72,3708.63 -2746.06,3713.98 MC3.2@-2746.06,3736.61
PORTB_S0_D0_P: J4.5 MC3.26 | length 2544.1
  L1-TOP w3.3: v1(-2550.78,3804.54) -2548.5,3804.54 -2540.5,3812.54 -2523.55,3812.54 -2504.5,3793.49 -2504.5,3764.59 -2509.84,3759.25 MC3.26@-2509.84,3736.61
  L6-BOT w3.3: v1(-2550.78,3804.54) -2548.5,3804.54 -2540.5,3812.54 -2523.69,3812.54 -2497.75,3838.49 -2497.75,4518 -2488.95,4526.8 -2397.44,4618.31 ccw(c-2407.81,4628.67) -2396.12,4637.53 -2396.12,4637.72 -2397.42,4639.02 ; -2397.45,4639.05 cw(c-2393.44,4643.04) -2397.44,4647.05 -2385.43,4659.05 cw(c-2381.43,4655.05) -2377.43,4659.05 -2363.36,4644.99 ccw(c-2353,4655.35) -2342.63,4644.99 -2330.59,4657.03 ccw(c-2340.99,4667.36) -2330.62,4677.73 -2357.3,4704.4 -2369.02,4716.12 cw(c-2365.01,4720.12) -2369.02,4724.12 -2357.01,4736.13 cw(c-2353.01,4732.12) -2348.99,4736.12 -2307.03,4694.15 ccw(c-2296.63,4704.49) -2286.27,4694.12 -2274.23,4706.17 ccw(c-2284.63,4716.5) -2272.94,4725.35 -2272.94,4725.54 -2316.27,4768.87 cw(c-2312.26,4772.87) -2316.27,4776.87 -2304.26,4788.88 cw(c-2300.26,4784.87) -2296.24,4788.87 -2254.28,4746.9 ccw(c-2243.88,4757.24) -2233.52,4746.87 -2221.48,4758.92 ccw(c-2231.88,4769.25) -2220.19,4778.1 -2220.19,4778.29 -2224.82,4782.92 cw(c-2220.82,4786.92) -2224.82,4790.93 -2220.47,4795.28 -2206.49,4809.26 -2206.49,5460.81 -2226.1,5480.41 -2226.1,5567.02 -2283.29,5624.22 -2310.85,5624.22 -2334.01,5647.38 -2334.01,5658.69 -2326.97,5665.72 v2(-2326.97,5667.97)
PORTB_S1_D1_P: J4.6 MC3.21 | length 2726.1
  L1-TOP w3.3: MC3.21@-2549.21,3979.92 -2549.21,4002.56 -2543.87,4007.9 -2543.87,4060.44 -2471.5,4132.81 -2471.5,4766.29 -2272.95,4964.84 -2271.78,4966.01 ccw(c-2275.78,4970.01) -2271.78,4974.02 -2277.75,4979.99 cw(c-2273.75,4983.99) -2277.75,4988 -2265.75,5000 cw(c-2261.74,4996) -2257.74,5000 -2251.77,4994.03 ccw(c-2247.76,4998.03) -2243.76,4994.03 -2228.44,5009.35 -2219.35,5018.44 -2219.35,5019.68 -2219.35,5036.35 ccw(c-2225.01,5036.35) -2225.01,5042.01 -2300.7,5042.01 cw(c-2300.7,5056.67) -2315.36,5056.67 -2315.36,5073.65 cw(c-2300.7,5073.65) -2300.7,5088.31 -2166.42,5088.31 ccw(c-2166.42,5093.97) -2160.76,5093.97 -2160.76,5110.95 ccw(c-2166.42,5110.95) -2166.42,5116.61 -2314.98,5116.61 cw(c-2314.98,5131.27) -2329.64,5131.27 -2329.64,5148.25 cw(c-2314.98,5148.25) -2314.98,5162.91 -2166.42,5162.91 ccw(c-2166.42,5168.57) -2160.76,5168.57 -2160.76,5185.55 ccw(c-2166.42,5185.55) -2166.42,5191.21 -2314.98,5191.21 cw(c-2314.98,5205.87) -2329.64,5205.87 -2329.64,5222.85 cw(c-2314.98,5222.85) -2314.98,5237.51 -2169.74,5237.51 ccw(c-2169.74,5243.17) -2164.08,5243.17 -2164.08,5260.15 ccw(c-2169.74,5260.15) -2169.74,5265.81 -2204.69,5265.81 cw(c-2204.69,5280.47) -2219.35,5280.47 -2219.35,5286.62 -2219.35,5441.41 -2236.4,5458.46 -2323.06,5458.46 -2334.01,5447.51 -2334.01,5444.04 -2332.07,5442.11 -2329.11,5442.11 -2322.76,5435.76 J4.6@-2322.76,5399.01
PORTB_S2_D0_N: J4.7 MC3.28 | length 2544
  L1-TOP w3.3: v1(-2550.78,3829.54) -2548.5,3829.54 -2540.5,3821.54 -2519.82,3821.54 -2495.5,3797.22 -2495.5,3764.59 -2490.16,3759.25 MC3.28@-2490.16,3736.61
  L6-BOT w3.3: v1(-2550.78,3829.54) -2548.5,3829.54 -2540.5,3821.54 -2527.42,3821.54 -2506.75,3842.22 -2506.75,4521.73 -2495.31,4533.16 -2403.8,4624.67 ccw(c-2407.81,4628.67) -2403.79,4632.67 ; -2403.83,4632.7 cw(c-2393.44,4643.04) -2403.8,4653.41 -2391.76,4665.45 cw(c-2381.43,4655.05) -2371.07,4665.42 -2357,4651.35 ccw(c-2353,4655.35) -2349,4651.35 -2336.99,4663.36 ccw(c-2340.99,4667.36) -2336.99,4671.36 -2375.35,4709.73 cw(c-2365.01,4720.12) -2375.38,4730.48 -2363.34,4742.53 cw(c-2353.01,4732.12) -2344.15,4743.81 -2343.96,4743.81 -2300.63,4700.48 ccw(c-2296.63,4704.49) -2292.63,4700.49 -2280.63,4712.49 ccw(c-2284.63,4716.5) -2280.64,4720.51 ; v2(-2350.04,5667.97) -2350.04,5665.72 -2343.01,5658.69 -2343.01,5643.65 -2314.58,5615.22 -2287.02,5615.22 -2235.1,5563.3 -2235.1,5476.68 -2215.49,5457.08 -2215.49,4812.98 -2226.84,4801.64 -2231.19,4797.29 ccw(c-2220.82,4786.92) -2231.19,4776.56 -2227.9,4773.28 ; -2280.65,4720.53 -2322.6,4762.47 cw(c-2312.26,4772.87) -2322.63,4783.23 -2310.59,4795.28 cw(c-2300.26,4784.87) -2291.4,4796.56 -2291.21,4796.56 -2247.88,4753.23 ccw(c-2243.88,4757.24) -2239.88,4753.24 -2227.88,4765.24 ccw(c-2231.88,4769.25) -2227.89,4773.26
PORTB_S3_D1_N: J4.8 MC3.23 | length 2726.1
  L1-TOP w3.3: MC3.23@-2529.53,3979.92 -2529.53,4002.56 -2534.87,4007.9 -2534.87,4056.71 -2462.5,4129.09 -2462.5,4762.56 -2266.58,4958.48 -2210.35,5014.71 -2210.35,5019.68 -2210.35,5036.35 ccw(c-2225.01,5036.35) -2225.01,5051.01 -2300.7,5051.01 cw(c-2300.7,5056.67) -2306.36,5056.67 -2306.36,5073.65 cw(c-2300.7,5073.65) -2300.7,5079.31 -2166.42,5079.31 ccw(c-2166.42,5093.97) -2151.76,5093.97 -2151.76,5110.95 ccw(c-2166.42,5110.95) -2166.42,5125.61 -2314.98,5125.61 cw(c-2314.98,5131.27) -2320.64,5131.27 -2320.64,5148.25 cw(c-2314.98,5148.25) -2314.98,5153.91 -2166.42,5153.91 ccw(c-2166.42,5168.57) -2151.76,5168.57 -2151.76,5185.55 ccw(c-2166.42,5185.55) -2166.42,5200.21 -2314.98,5200.21 cw(c-2314.98,5205.87) -2320.64,5205.87 -2320.64,5222.85 cw(c-2314.98,5222.85) -2314.98,5228.51 -2169.74,5228.51 ccw(c-2169.74,5243.17) -2155.08,5243.17 -2155.08,5260.15 ccw(c-2169.74,5260.15) -2169.74,5274.81 -2204.69,5274.81 cw(c-2204.69,5280.47) -2210.35,5280.47 -2210.35,5286.62 -2210.35,5445.14 -2232.67,5467.46 -2326.78,5467.46 -2343.01,5451.24 -2343.01,5444.04 -2344.94,5442.11 -2347.91,5442.11 -2354.26,5435.76 J4.8@-2354.26,5399.01
PORTB_S4_D2_P: J4.9 MC3.22 | length 2544.2
  L1-TOP w3.3: v1(-2551.87,3653.54) -2551.87,3655.83 -2543.87,3663.83 -2543.87,3708.63 -2549.21,3713.98 MC3.22@-2549.21,3736.61
  L6-BOT w3.3: v1(-2551.87,3653.54) -2551.87,3655.83 -2543.87,3663.83 -2543.87,3681.42 -2614.17,3751.72 -2614.17,3788.32 -2600.68,3801.82 -2600.68,3881.98 -2557.37,3925.29 -2557.37,4719.14 -2545.73,4730.77 -2475.85,4800.65 cw(c-2465.49,4790.29) -2456.63,4801.97 -2456.44,4801.97 -2455.14,4800.67 ccw(c-2451.12,4804.65) -2447.12,4800.65 -2435.11,4812.66 ccw(c-2439.11,4816.66) -2435.11,4820.66 -2452.15,4837.7 cw(c-2441.78,4848.07) -2452.15,4858.43 -2440.1,4870.47 cw(c-2429.77,4860.07) -2419.41,4870.44 -2396.84,4847.87 -2386.92,4837.95 ccw(c-2382.93,4841.96) -2378.92,4837.96 -2366.92,4849.97 ccw(c-2370.92,4853.97) -2366.93,4857.98 ; v2(-2390.07,5581.25) -2390.07,5583.5 -2397.11,5590.54 -2397.11,5593.95 -2394.09,5596.96 -2359.15,5596.96 -2317.77,5555.58 -2317.77,5501.34 -2317.77,5482.29 cw(c-2323.43,5482.29) -2323.43,5476.63 -2331.87,5476.63 ccw(c-2331.87,5470.97) -2337.53,5470.97 -2337.53,5453.99 ccw(c-2331.87,5453.99) -2331.87,5448.33 -2323.43,5448.33 cw(c-2323.43,5442.67) -2317.77,5442.67 -2317.77,5441.02 -2317.77,4958.73 -2325.26,4951.25 -2329.61,4946.9 ccw(c-2319.24,4936.53) -2329.61,4926.16 -2314.2,4910.75 ; -2366.95,4858 -2400.01,4891.06 cw(c-2389.67,4901.46) -2400.04,4911.82 -2388,4923.87 cw(c-2377.67,4913.47) -2368.81,4925.15 -2368.62,4925.15 -2334.17,4890.7 ccw(c-2330.18,4894.71) -2326.17,4890.71 -2314.17,4902.72 ccw(c-2318.17,4906.72) -2314.18,4910.73
PORTB_S5_D3_P: J4.10 MC3.25 | length 2726.1
  L1-TOP w3.3: MC3.25@-2509.84,3979.92 -2509.84,4002.56 -2504.5,4007.9 -2504.5,4038.94 -2434.2,4109.25 -2434.2,4750.84 -2059.06,5125.98 -2059.06,5127.57 -2059.06,5157.11 cw(c-2044.4,5157.11) -2044.4,5171.77 -1993.14,5171.77 ccw(c-1993.14,5177.43) -1987.48,5177.43 -1987.48,5194.41 ccw(c-1993.14,5194.41) -1993.14,5200.07 -2112.12,5200.07 cw(c-2112.12,5214.73) -2126.78,5214.73 -2126.78,5231.71 cw(c-2112.12,5231.71) -2112.12,5246.37 -1991.26,5246.37 ccw(c-1991.26,5252.03) -1985.6,5252.03 -1985.6,5269.01 ccw(c-1991.26,5269.01) -1991.26,5274.67 -2112.12,5274.67 cw(c-2112.12,5289.33) -2126.78,5289.33 -2126.78,5306.31 cw(c-2112.12,5306.31) -2112.12,5320.97 -1991.26,5320.97 ccw(c-1991.26,5326.63) -1985.6,5326.63 -1985.6,5343.61 ccw(c-1991.26,5343.61) -1991.26,5349.27 -2044.4,5349.27 cw(c-2044.4,5363.93) -2059.06,5363.93 -2059.06,5370.08 -2059.06,5379.54 -2064.56,5385.05 -2077.65,5398.14 ccw(c-2081.65,5394.14) -2085.66,5398.14 -2091.63,5392.17 cw(c-2095.63,5396.17) -2099.64,5392.17 -2111.64,5404.17 cw(c-2107.64,5408.17) -2111.64,5412.18 -2105.67,5418.15 ccw(c-2109.67,5422.15) -2105.67,5426.16 -2126.85,5447.33 -2164.89,5485.38 -2362.67,5485.38 -2397.01,5451.04 -2397.01,5444.04 -2395.07,5442.11 -2392.11,5442.11 -2385.76,5435.76 J4.10@-2385.76,5399.01
PORTB_S6_D2_N: J4.11 MC3.24 | length 2544.2
  L1-TOP w3.3: MC3.24@-2529.53,3736.61 -2529.53,3713.98 -2534.87,3708.63 -2534.87,3663.83 -2526.87,3655.83 v1(-2526.87,3653.54)
  L6-BOT w3.3: v1(-2526.87,3653.54) -2526.87,3655.83 -2534.87,3663.83 -2534.87,3685.15 -2605.17,3755.45 -2605.17,3784.59 -2591.68,3798.09 -2591.68,3878.26 -2548.37,3921.56 -2548.37,3964.57 -2548.37,4035.43 -2548.37,4715.41 -2539.37,4724.41 -2469.49,4794.29 cw(c-2465.49,4790.29) -2461.5,4794.3 ; -2461.46,4794.27 ccw(c-2451.12,4804.65) -2440.75,4794.29 -2428.71,4806.33 ccw(c-2439.11,4816.66) -2428.75,4827.03 -2445.78,4844.06 cw(c-2441.78,4848.07) -2445.78,4852.07 -2433.77,4864.07 cw(c-2429.77,4860.07) -2425.77,4864.07 -2393.32,4831.62 ccw(c-2382.93,4841.96) -2372.56,4831.6 -2360.52,4843.64 ccw(c-2370.92,4853.97) -2359.23,4862.82 -2359.23,4863.02 -2393.68,4897.46 cw(c-2389.67,4901.46) -2393.67,4905.46 -2381.67,4917.47 cw(c-2377.67,4913.47) -2373.65,4917.46 ; v2(-2413.14,5581.25) -2413.14,5583.5 -2406.11,5590.54 -2406.11,5597.67 -2397.82,5605.96 -2355.42,5605.96 -2308.77,5559.31 -2308.77,4955.01 -2318.9,4944.88 -2323.25,4940.53 ccw(c-2319.24,4936.53) -2323.25,4932.53 -2306.48,4915.77 -2306.48,4915.57 cw(c-2318.17,4906.72) -2307.77,4896.39 -2319.81,4884.35 cw(c-2330.18,4894.71) -2340.57,4884.37 -2373.63,4917.44
PORTB_S7_D3_N: J4.12 MC3.27 | length 2726.1
  L1-TOP w3.3: MC3.27@-2490.16,3979.92 -2490.16,4002.56 -2495.5,4007.9 -2495.5,4035.21 -2425.2,4105.52 -2425.2,4747.11 -2050.06,5122.26 -2050.06,5127.57 -2050.06,5157.11 cw(c-2044.4,5157.11) -2044.4,5162.77 -1993.14,5162.77 ccw(c-1993.14,5177.43) -1978.48,5177.43 -1978.48,5194.41 ccw(c-1993.14,5194.41) -1993.14,5209.07 -2112.12,5209.07 cw(c-2112.12,5214.73) -2117.78,5214.73 -2117.78,5231.71 cw(c-2112.12,5231.71) -2112.12,5237.37 -1991.26,5237.37 ccw(c-1991.26,5252.03) -1976.6,5252.03 -1976.6,5269.01 ccw(c-1991.26,5269.01) -1991.26,5283.67 -2112.12,5283.67 cw(c-2112.12,5289.33) -2117.78,5289.33 -2117.78,5306.31 cw(c-2112.12,5306.31) -2112.12,5311.97 -1991.26,5311.97 ccw(c-1991.26,5326.63) -1976.6,5326.63 -1976.6,5343.61 ccw(c-1991.26,5343.61) -1991.26,5358.27 -2044.4,5358.27 cw(c-2044.4,5363.93) -2050.06,5363.93 -2050.06,5370.08 -2050.06,5383.27 -2161.16,5494.38 -2366.4,5494.38 -2406.01,5454.77 -2406.01,5444.04 -2407.94,5442.11 -2410.91,5442.11 -2417.26,5435.76 J4.12@-2417.26,5399.01
PORTB_S8_D4_P: J4.13 MC3.14 | length 2544.3
  L1-TOP w3.3: v1(-2665.69,3804.57) -2663.41,3804.57 -2655.41,3812.57 -2651.23,3812.57 -2622.61,3783.95 -2622.61,3764.59 -2627.95,3759.25 MC3.14@-2627.95,3736.61
  L6-BOT w3.3: v1(-2665.69,3804.57) -2663.41,3804.57 -2655.41,3812.57 -2646.42,3812.57 -2629.79,3829.2 -2629.79,3895.26 -2599.55,3925.5 -2599.55,4888.64 -2590.55,4897.64 -2550.2,4937.99 ; -2550.2,4937.99 cw(c-2546.2,4933.99) -2542.18,4937.97 -2515.27,4911.07 ccw(c-2504.91,4921.44) -2494.54,4911.07 -2482.5,4923.11 ccw(c-2492.9,4933.44) -2482.54,4943.81 -2513.52,4974.8 -2527.14,4988.41 cw(c-2523.13,4992.41) -2527.13,4996.41 -2515.13,5008.42 cw(c-2511.12,5004.42) -2507.11,5008.41 ; -2507.09,5008.39 -2457.83,4959.12 ccw(c-2447.43,4969.46) -2437.07,4959.09 -2425.02,4971.14 ccw(c-2435.43,4981.47) -2423.74,4990.32 -2423.74,4990.52 -2474.39,5041.16 cw(c-2470.38,5045.16) -2474.38,5049.16 -2462.38,5061.17 cw(c-2458.37,5057.17) -2454.36,5061.16 ; -2454.34,5061.14 -2405.08,5011.87 ccw(c-2394.68,5022.21) -2384.32,5011.84 -2372.27,5023.89 ccw(c-2382.68,5034.22) -2370.99,5043.07 -2370.99,5043.27 -2403.96,5076.23 cw(c-2399.95,5080.23) -2403.96,5084.23 -2399.61,5088.58 -2395.35,5092.84 -2395.35,5460.42 -2434.84,5499.91 -2434.84,5523.8 -2460.01,5548.97 -2460.01,5658.69 -2452.97,5665.72 v2(-2452.97,5667.97)
PORTB_S9_D5_P: J4.14 MC3.18 | length 2544.6
  L1-TOP w3.3: v1(-2665.35,3639.17) -2663.07,3639.17 -2655.07,3631.17 -2643.43,3631.17 -2583.24,3691.37 -2583.24,3708.63 -2588.58,3713.98 MC3.18@-2588.58,3736.61
  L6-BOT w3.3: v1(-2665.35,3639.17) -2667.64,3639.17 -2675.64,3631.17 -2682.42,3631.17 -2703.65,3652.41 -2703.65,3665.35 -2703.65,3695.3 cw(c-2697.99,3695.3) -2697.99,3700.96 -2689.55,3700.96 ccw(c-2689.55,3706.62) -2683.89,3706.62 -2683.89,3723.6 ccw(c-2689.55,3723.6) -2689.55,3729.26 -2697.99,3729.26 cw(c-2697.99,3734.92) -2703.65,3734.92 -2703.65,3758.13 -2703.65,3880.45 -2655.23,3928.88 -2655.23,5061.31 -2649.61,5066.93 -2637.52,5079.01 cw(c-2633.52,5075.01) -2629.52,5079.01 -2606.44,5055.93 ccw(c-2596.07,5066.29) -2585.7,5055.93 -2573.66,5067.97 ccw(c-2584.06,5078.3) -2573.7,5088.66 -2602.02,5116.99 -2614.46,5129.43 cw(c-2610.46,5133.43) -2614.46,5137.43 -2602.45,5149.44 cw(c-2598.45,5145.44) -2594.44,5149.43 -2530.03,5085.02 ccw(c-2519.64,5095.36) -2509.27,5084.99 -2497.23,5097.04 ccw(c-2507.63,5107.37) -2495.95,5116.22 -2495.95,5116.41 -2561.71,5182.18 cw(c-2557.71,5186.18) -2561.71,5190.18 -2549.7,5202.19 cw(c-2545.7,5198.19) -2541.69,5202.18 -2477.28,5137.77 ccw(c-2466.89,5148.11) -2456.52,5137.74 -2444.48,5149.79 ccw(c-2454.88,5160.12) -2443.2,5168.97 -2443.2,5169.16 -2491.28,5217.25 cw(c-2487.28,5221.25) -2491.28,5225.25 -2486.93,5229.6 -2460.11,5256.43 -2460.11,5346.37 -2453.07,5353.41 v2(-2453.07,5355.65)
PORTB_S10_D4_N: J4.15 MC3.16 | length 2544.4
  L1-TOP w3.3: v1(-2665.69,3829.57) -2663.41,3829.57 -2655.41,3821.57 -2647.5,3821.57 -2613.61,3787.68 -2613.61,3764.59 -2608.27,3759.25 MC3.16@-2608.27,3736.61
  L6-BOT w3.3: v1(-2665.69,3829.57) -2663.41,3829.57 -2655.41,3821.57 -2650.14,3821.57 -2638.79,3832.93 -2638.79,3898.99 -2608.55,3929.23 -2608.55,4892.37 -2596.92,4904 -2556.56,4944.35 cw(c-2546.2,4933.99) -2537.34,4945.67 -2537.15,4945.67 -2535.85,4944.37 -2527.62,4936.14 -2508.91,4917.43 ccw(c-2504.91,4921.44) -2500.91,4917.43 -2488.9,4929.44 ccw(c-2492.9,4933.44) -2488.9,4937.44 -2533.47,4982.02 cw(c-2523.13,4992.41) -2533.5,5002.78 -2521.45,5014.82 cw(c-2511.12,5004.42) -2502.27,5016.1 -2502.08,5016.1 -2451.43,4965.45 ccw(c-2447.43,4969.46) -2443.43,4965.46 -2431.42,4977.47 ccw(c-2435.43,4981.47) -2431.43,4985.48 ; v2(-2476.04,5667.97) -2476.04,5665.72 -2469.01,5658.69 -2469.01,5545.24 -2443.84,5520.07 -2443.84,5496.19 -2404.35,5456.69 -2404.35,5096.57 -2405.97,5094.95 -2410.32,5090.6 ccw(c-2399.95,5080.23) -2410.32,5069.87 -2378.7,5038.25 ; -2431.45,4985.5 -2480.72,5034.76 cw(c-2470.38,5045.16) -2480.75,5055.53 -2468.7,5067.57 cw(c-2458.37,5057.17) -2449.52,5068.85 -2449.33,5068.85 -2398.68,5018.2 ccw(c-2394.68,5022.21) -2390.68,5018.21 -2378.67,5030.22 ccw(c-2382.68,5034.22) -2378.68,5038.23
